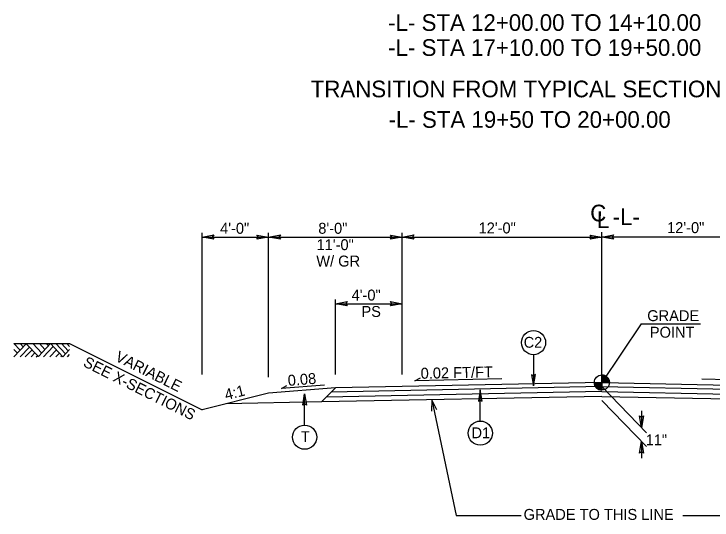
# Model space of a CAD drawing. Extents: x 1901984 to 1902132, y 194049 to 194156.
# Drawn here: x 1901983.55 to 1902025.49, y 194096.32 to 194126.7 of the extents above; entities that cross this region are included whole.
import ezdxf

# ---------------------------------------------------------------- set-up
doc = ezdxf.new("R2010")
doc.units = 0
for name, color, linetype in [('Old_Level_1', 7, 'Continuous'), ('Old_Level_11', 7, 'Continuous'), ('Old_Level_2', 7, 'Continuous'), ('Old_Level_20', 7, 'Continuous'), ('Old_Level_3', 7, 'Continuous'), ('Scratch_Level_3', 7, 'Continuous')]:
    doc.layers.add(name, color=color, linetype=linetype)

# ---------------------------------------------------------------- blocks, each defined once
blk = doc.blocks.new('TERMINATOR')
at = {"layer": 'Scratch_Level_3'}
blk.add_lwpolyline([(-0.469, 0.081), (0, 0), (-0.471, -0.083), (-0.411, 0)], close=True, dxfattribs=at)

msp = doc.modelspace()

# ---------------------------------------------------------------- linework, layer by layer
at = {"layer": 'Old_Level_1'}
for p, q in [((1901994.851, 194105.058), (1901994.851, 194113.558)), ((1901998.851, 194104.896), (1901998.851, 194113.558)), ((1902006.87, 194105.058), (1902006.87, 194113.558)), ((1902018.869, 194104.578), (1902018.869, 194113.598)), ((1901994.851, 194113.308), (1901998.851, 194113.308)), ((1901998.851, 194113.308), (1902006.87, 194113.308)), ((1902006.87, 194113.308), (1902018.869, 194113.308)), ((1902030.869, 194113.308), (1902018.869, 194113.308)), ((1902002.87, 194105.058), (1902002.87, 194109.558)), ((1902002.87, 194109.308), (1902006.87, 194109.308)), ((1901986.894, 194106.915), (1901994.851, 194102.936)), ((1902018.869, 194104.578), (1902018.869, 194105.028)), ((1902007.634, 194104.68), (1902007.967, 194104.847)), ((1902012.866, 194104.79), (1902007.634, 194104.68)), ((1902024.872, 194104.79), (1902030.105, 194104.68)), ((1902002.87, 194104.258), (1901998.851, 194103.936)), ((1902002.206, 194104.425), (1901999.626, 194104.218)), ((1901999.626, 194104.218), (1901999.949, 194104.405)), ((1902002.87, 194104.258), (1902002.019, 194103.407)), ((1902018.869, 194104.328), (1902002.614, 194104.003)), ((1902017.869, 194104.558), (1902002.87, 194104.258)), ((1902018.869, 194104.578), (1902017.869, 194104.558)), ((1902018.419, 194104.578), (1902018.869, 194104.578)), ((1902018.868, 194104.128), (1902018.869, 194104.578)), ((1902018.869, 194104.578), (1902018.868, 194104.128)), ((1902019.319, 194104.578), (1902018.869, 194104.578)), ((1902018.869, 194104.578), (1902019.869, 194104.558)), ((1902018.869, 194104.328), (1902035.124, 194104.003)), ((1902018.869, 194104.328), (1902021.548, 194101.561)), ((1902019.869, 194104.558), (1902034.869, 194104.258)), ((1901998.851, 194103.936), (1901994.851, 194102.936)), ((1902018.869, 194104.036), (1902002.317, 194103.705)), ((1902018.869, 194104.036), (1902035.422, 194103.705)), ((1902002.019, 194103.407), (1901996.276, 194103.292)), ((1902018.869, 194103.744), (1902002.019, 194103.407)), ((1902008.655, 194103.54), (1902010.107, 194096.598)), ((1902018.869, 194103.744), (1902035.719, 194103.407)), ((1902018.869, 194103.494), (1902021.548, 194100.727)), ((1902021.245, 194102.873), (1902021.245, 194101.873)), ((1902021.245, 194101.039), (1902021.245, 194100.039)), ((1902010.107, 194096.598), (1902014.016, 194096.598)), ((1902023.723, 194096.598), (1902027.632, 194096.598))]:
    msp.add_line(p, q, dxfattribs=at)
for points in [[(1901983.552, 194106.915), (1901986.894, 194106.915)], [(1902018.873, 194105.028), (1902018.873, 194105.028), (1902018.873, 194104.578)], [(1902018.882, 194105.028), (1902018.882, 194104.578)], [(1902018.891, 194105.027), (1902018.891, 194104.578)], [(1902018.9, 194105.027), (1902018.9, 194104.578)], [(1902018.909, 194105.026), (1902018.909, 194104.578)], [(1902018.918, 194105.025), (1902018.918, 194104.578)], [(1902018.927, 194105.024), (1902018.927, 194104.578)], [(1902018.936, 194105.023), (1902018.936, 194104.578)], [(1902018.945, 194105.022), (1902018.945, 194104.578)], [(1902018.954, 194105.02), (1902018.954, 194104.578)], [(1902018.963, 194105.018), (1902018.963, 194104.578)], [(1902018.972, 194105.016), (1902018.972, 194104.578)], [(1902018.981, 194105.014), (1902018.981, 194104.578)], [(1902018.99, 194105.011), (1902018.99, 194104.578)], [(1902018.999, 194105.009), (1902018.999, 194104.578)], [(1902019.008, 194105.006), (1902019.008, 194104.578)], [(1902019.017, 194105.003), (1902019.017, 194104.578)], [(1902019.026, 194105), (1902019.026, 194104.578)], [(1902019.035, 194104.996), (1902019.035, 194104.578)], [(1902019.044, 194104.992), (1902019.044, 194104.578)], [(1902019.053, 194104.988), (1902019.053, 194104.578)], [(1902019.062, 194104.984), (1902019.062, 194104.578)], [(1902019.071, 194104.98), (1902019.071, 194104.578)], [(1902019.08, 194104.975), (1902019.08, 194104.578)], [(1902019.089, 194104.97), (1902019.089, 194104.578)], [(1902019.098, 194104.965), (1902019.098, 194104.578)], [(1902019.107, 194104.96), (1902019.107, 194104.578)], [(1902019.116, 194104.954), (1902019.116, 194104.578)], [(1902019.125, 194104.948), (1902019.125, 194104.578)], [(1902019.134, 194104.941), (1902019.134, 194104.578)], [(1902019.143, 194104.935), (1902019.143, 194104.578)], [(1902019.152, 194104.928), (1902019.152, 194104.578)], [(1902019.161, 194104.92), (1902019.161, 194104.578)], [(1902019.17, 194104.912), (1902019.17, 194104.578)], [(1902019.179, 194104.904), (1902019.179, 194104.578)], [(1902019.188, 194104.895), (1902019.188, 194104.578)], [(1902019.197, 194104.886), (1902019.197, 194104.578)], [(1902019.206, 194104.876), (1902019.206, 194104.578)], [(1902019.215, 194104.865), (1902019.215, 194104.578)], [(1902019.224, 194104.854), (1902019.224, 194104.578)], [(1902019.233, 194104.842), (1902019.233, 194104.578)], [(1902019.242, 194104.829), (1902019.242, 194104.578)], [(1902019.251, 194104.815), (1902019.251, 194104.578)], [(1902019.26, 194104.8), (1902019.26, 194104.578)], [(1902019.269, 194104.784), (1902019.269, 194104.578)], [(1902019.278, 194104.765), (1902019.278, 194104.578)], [(1902019.287, 194104.744), (1902019.287, 194104.578)], [(1902019.296, 194104.719), (1902019.296, 194104.578)], [(1902019.305, 194104.688), (1902019.305, 194104.578)], [(1902019.314, 194104.642), (1902019.314, 194104.578)], [(1902018.421, 194104.578), (1902018.421, 194104.529)], [(1902018.43, 194104.578), (1902018.43, 194104.476)], [(1902018.439, 194104.578), (1902018.439, 194104.444)], [(1902018.448, 194104.578), (1902018.448, 194104.417)], [(1902018.457, 194104.578), (1902018.457, 194104.396)], [(1902018.466, 194104.578), (1902018.466, 194104.377)], [(1902018.475, 194104.578), (1902018.475, 194104.36)], [(1902018.484, 194104.578), (1902018.484, 194104.344)], [(1902018.493, 194104.578), (1902018.493, 194104.33)], [(1902018.502, 194104.578), (1902018.502, 194104.317)], [(1902018.511, 194104.578), (1902018.511, 194104.305)], [(1902018.52, 194104.578), (1902018.52, 194104.294)], [(1902018.529, 194104.578), (1902018.529, 194104.283)], [(1902018.538, 194104.578), (1902018.538, 194104.273)], [(1902018.547, 194104.578), (1902018.547, 194104.263)], [(1902018.556, 194104.578), (1902018.556, 194104.254)], [(1902018.565, 194104.578), (1902018.565, 194104.246)], [(1902018.574, 194104.578), (1902018.574, 194104.238)], [(1902018.583, 194104.578), (1902018.583, 194104.23)], [(1902018.592, 194104.578), (1902018.592, 194104.223)], [(1902018.601, 194104.578), (1902018.601, 194104.216)], [(1902018.61, 194104.578), (1902018.61, 194104.21)], [(1902018.619, 194104.578), (1902018.619, 194104.204)], [(1902018.628, 194104.578), (1902018.628, 194104.198)], [(1902018.637, 194104.578), (1902018.637, 194104.192)], [(1902018.646, 194104.578), (1902018.646, 194104.187)], [(1902018.655, 194104.578), (1902018.655, 194104.182)], [(1902018.664, 194104.578), (1902018.664, 194104.177)], [(1902018.673, 194104.578), (1902018.673, 194104.173)], [(1902018.682, 194104.578), (1902018.682, 194104.169)], [(1902018.691, 194104.578), (1902018.691, 194104.165)], [(1902018.7, 194104.578), (1902018.7, 194104.161)], [(1902018.709, 194104.578), (1902018.709, 194104.157)], [(1902018.718, 194104.578), (1902018.718, 194104.154)], [(1902018.727, 194104.578), (1902018.727, 194104.151)], [(1902018.736, 194104.578), (1902018.736, 194104.148)], [(1902018.745, 194104.578), (1902018.745, 194104.146)], [(1902018.754, 194104.578), (1902018.754, 194104.143)], [(1902018.763, 194104.578), (1902018.763, 194104.141)], [(1902018.772, 194104.578), (1902018.772, 194104.139)], [(1902018.781, 194104.578), (1902018.781, 194104.137)], [(1902018.79, 194104.578), (1902018.79, 194104.135)], [(1902018.799, 194104.578), (1902018.799, 194104.134)], [(1902018.808, 194104.578), (1902018.808, 194104.132)], [(1902018.817, 194104.578), (1902018.817, 194104.131)], [(1902018.826, 194104.578), (1902018.826, 194104.13)], [(1902018.835, 194104.578), (1902018.835, 194104.129)], [(1902018.844, 194104.578), (1902018.844, 194104.129)], [(1902018.853, 194104.578), (1902018.853, 194104.128)], [(1902018.862, 194104.578), (1902018.862, 194104.128), (1902018.862, 194104.128)], [(1902008.948, 194102.931), (1902008.655, 194103.54), (1902008.627, 194102.864)]]:
    msp.add_lwpolyline(points, dxfattribs=at)
msp.add_circle((1902018.869, 194104.578), 0.45, dxfattribs=at)
for start, end in [(359.9905, 89.9905), (179.9905, 269.9905)]:
    msp.add_arc((1902018.869, 194104.578), 0.45, start, end, dxfattribs=at)
at = {"layer": 'Old_Level_11'}
for p, q in [((1901983.552, 194106.915), (1901983.927, 194106.512)), ((1901983.552, 194106.11), (1901984.294, 194106.907)), ((1901983.926, 194106.11), (1901984.48, 194106.706)), ((1901983.927, 194106.915), (1901984.114, 194106.714)), ((1901984.294, 194106.907), (1901985.018, 194106.128)), ((1901984.685, 194106.915), (1901985.218, 194106.342)), ((1901985.018, 194106.128), (1901985.749, 194106.914)), ((1901985.083, 194106.915), (1901985.416, 194106.556)), ((1901985.328, 194106.11), (1901985.914, 194106.738)), ((1901985.485, 194106.915), (1901985.618, 194106.772)), ((1901985.749, 194106.914), (1901986.49, 194106.118)), ((1901986.071, 194106.915), (1901986.651, 194106.292)), ((1901986.404, 194106.915), (1901986.818, 194106.471)), ((1901986.724, 194106.915), (1901986.894, 194106.732)), ((1901983.552, 194106.553), (1901983.758, 194106.331)), ((1901984.235, 194106.11), (1901984.636, 194106.539)), ((1901984.582, 194106.11), (1901984.809, 194106.353)), ((1901985.698, 194106.11), (1901986.098, 194106.539)), ((1901986.064, 194106.11), (1901986.281, 194106.343)), ((1901986.49, 194106.118), (1901986.894, 194106.553)), ((1901984.893, 194106.11), (1901984.964, 194106.186)), ((1901986.359, 194106.11), (1901986.428, 194106.184)), ((1901986.76, 194106.11), (1901986.894, 194106.253)), ((1902014.762, 194106.246), (1902014.762, 194104.372)), ((1902001.013, 194102.018), (1902001.013, 194103.893)), ((1902011.566, 194102.261), (1902011.566, 194104.135))]:
    msp.add_line(p, q, dxfattribs=at)
for points in [[(1902014.646, 194105.043), (1902014.762, 194104.372), (1902014.881, 194105.047), (1902014.762, 194104.961)], [(1902000.897, 194103.221), (1902001.013, 194103.893), (1902001.132, 194103.217), (1902001.013, 194103.303)], [(1902011.682, 194103.464), (1902011.566, 194104.135), (1902011.447, 194103.46), (1902011.566, 194103.546)]]:
    msp.add_lwpolyline(points, close=True, dxfattribs=at)
for centre in [(1902014.762, 194106.971), (1902011.566, 194101.536), (1902001.013, 194101.293)]:
    msp.add_circle(centre, 0.725, dxfattribs=at)
at = {"layer": 'Old_Level_3'}
for q in [(1902018.869, 194104.578), (1902024.784, 194108.102)]:
    msp.add_line((1902021.221, 194108.102), q, dxfattribs=at)

# ---------------------------------------------------------------- block references
at = {"layer": 'Old_Level_1', "xscale": 1.5, "yscale": 1.5}
for p, rotation in [((1901994.851, 194113.308), 180), ((1901998.851, 194113.308), 180), ((1902006.87, 194113.308), 180), ((1902018.869, 194113.308), 180), ((1902002.87, 194109.308), 180), ((1902021.245, 194101.873), -90), ((1902021.245, 194101.039), 90)]:
    msp.add_blockref('TERMINATOR', p, dxfattribs=dict(at, rotation=rotation))
for p in [(1901998.851, 194113.308), (1902006.87, 194113.308), (1902018.869, 194113.308), (1902006.87, 194109.308)]:
    msp.add_blockref('TERMINATOR', p, dxfattribs=at)

# ---------------------------------------------------------------- texts
at = {"layer": 'Old_Level_1'}
for s, p in [('4\'-0" ', (1901995.936, 194113.506)), ('12\'-0" ', (1902011.463, 194113.526)), ('12\'-0" ', (1902022.787, 194113.546)), ('GRADE TO THIS LINE', (1902014.167, 194096.33))]:
    msp.add_text(s, height=0.656, dxfattribs=at).set_placement(p)
for s, rotation, p in [('8\'-0"', 360, (1902001.833, 194113.505)), ('11\'-0"', 360, (1902001.731, 194112.521)), ('W/ GR', 360, (1902001.714, 194111.537)), ('4\'-0"', 360, (1902003.834, 194109.496)), ('PS', 360, (1902004.425, 194108.512)), ('VARIABLE', 333.4349, (1901989.583, 194105.911)), ('SEE X-SECTIONS', 333.4349, (1901987.658, 194105.581)), ('4:1', 14.0362, (1901996.297, 194103.511))]:
    msp.add_text(s, height=0.656, rotation=rotation, dxfattribs=at).set_placement(p)
at = {"layer": 'Old_Level_11'}
for s, height, p in [('-L- STA 12+00.00 TO 14+10.00', 1, (1902006.031, 194125.683)), ('-L- STA 17+10.00 TO 19+50.00', 1, (1902006.031, 194124.183)), ('TRANSITION FROM TYPICAL SECTION NO.  1 TO EXISTING:', 1, (1902001.379, 194121.697)), ('-L- STA 19+50 TO 20+00.00', 1, (1902006.055, 194119.865)), ('GRADE', 0.656, (1902021.593, 194108.26)), ('POINT', 0.656, (1902021.751, 194107.266))]:
    msp.add_text(s, height=height, dxfattribs=at).set_placement(p)
at = {"layer": 'Old_Level_2'}
msp.add_text('C', height=1, dxfattribs=at).set_placement((1902018.168, 194114.249))
for s, height, rotation, p in [('L', 1, 359.9469, (1902018.57, 194113.845)), ('-L-', 1, 359.9469, (1902019.518, 194114.028)), ('0.02 FT/FT', 0.656, 1.1916, (1902007.989, 194104.799)), ('0.08', 0.656, 4.5739, (1902000.026, 194104.367))]:
    msp.add_text(s, height=height, rotation=rotation, dxfattribs=at).set_placement(p)
at = {"layer": 'Old_Level_20'}
for s, height, p in [('C2', 0.6491, (1902014.173, 194106.665)), ('D1', 0.6491, (1902011.044, 194101.232)), ('T', 0.649, (1902000.785, 194101)), ('11"', 0.6491, (1902021.507, 194100.809))]:
    msp.add_text(s, height=height, dxfattribs=at).set_placement(p)

doc.saveas('drawing.dxf')
